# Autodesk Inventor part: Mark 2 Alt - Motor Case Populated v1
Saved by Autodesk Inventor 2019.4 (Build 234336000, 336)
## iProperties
Created: 2020-06
Part Number: Mark 2 Alt - Motor Case Populated v1
Material: Generic
Document SubType Name: Modeling
Designer: Administrator
Density: 1 g/cm^3
Appearance: Default
Author: Administrator
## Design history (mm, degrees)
feature "Body7"
body "Solid1"
